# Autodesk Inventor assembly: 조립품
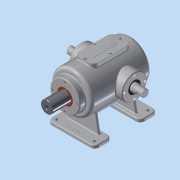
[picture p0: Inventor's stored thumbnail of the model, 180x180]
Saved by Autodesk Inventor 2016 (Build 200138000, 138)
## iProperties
Created: 2018-11
Part Number: 조립품
Material: 일반
Document SubType Name: Assembly
Designer: user
Mass: 8191.31 g
Surface Area: 4241.88 cm^2
Volume: 1855.5 cm^3
Density: 4.4146 g/cm^3
Author: user
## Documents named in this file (15)
- C:\Users\user\Desktop\381121V1005\조립품.iam
- C:\Users\user\Desktop\381121V1005\가변스프링.ipt
- C:\Users\user\Desktop\381121V1005\베어링 6205.ipt
- 베어링 6205.ipt
- C:\Users\user\Desktop\381121V1005\본체.ipt
- C:\Users\user\Desktop\381121V1005\볼트 M4x0.7.ipt
- C:\Users\user\Desktop\381121V1005\부시.ipt
- C:\Users\user\Desktop\381121V1005\상부커버.ipt
- C:\Users\user\Desktop\381121V1005\슬라이드 커버.ipt
- C:\Users\user\Desktop\381121V1005\슬라이드.ipt
- C:\Users\user\Desktop\381121V1005\오일실.ipt
- 오일실.ipt
- C:\Users\user\Desktop\381121V1005\육각머리볼트 M4.ipt
- C:\Users\user\Desktop\381121V1005\축 커버.ipt
- C:\Users\user\Desktop\381121V1005\편심축.ipt
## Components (13 placed, 2 different names)
1. 가변스프링:1
2. M4x0.7:3
3. M4x0.7:4
4. M4x0.7:5
5. M4x0.7:6
6. M4x0.7:1
7. M4x0.7:7
8. M4x0.7:8
9. M4x0.7:9
10. M4x0.7:2
11. M4x0.7:10
12. M4x0.7:11
13. M4x0.7:12
